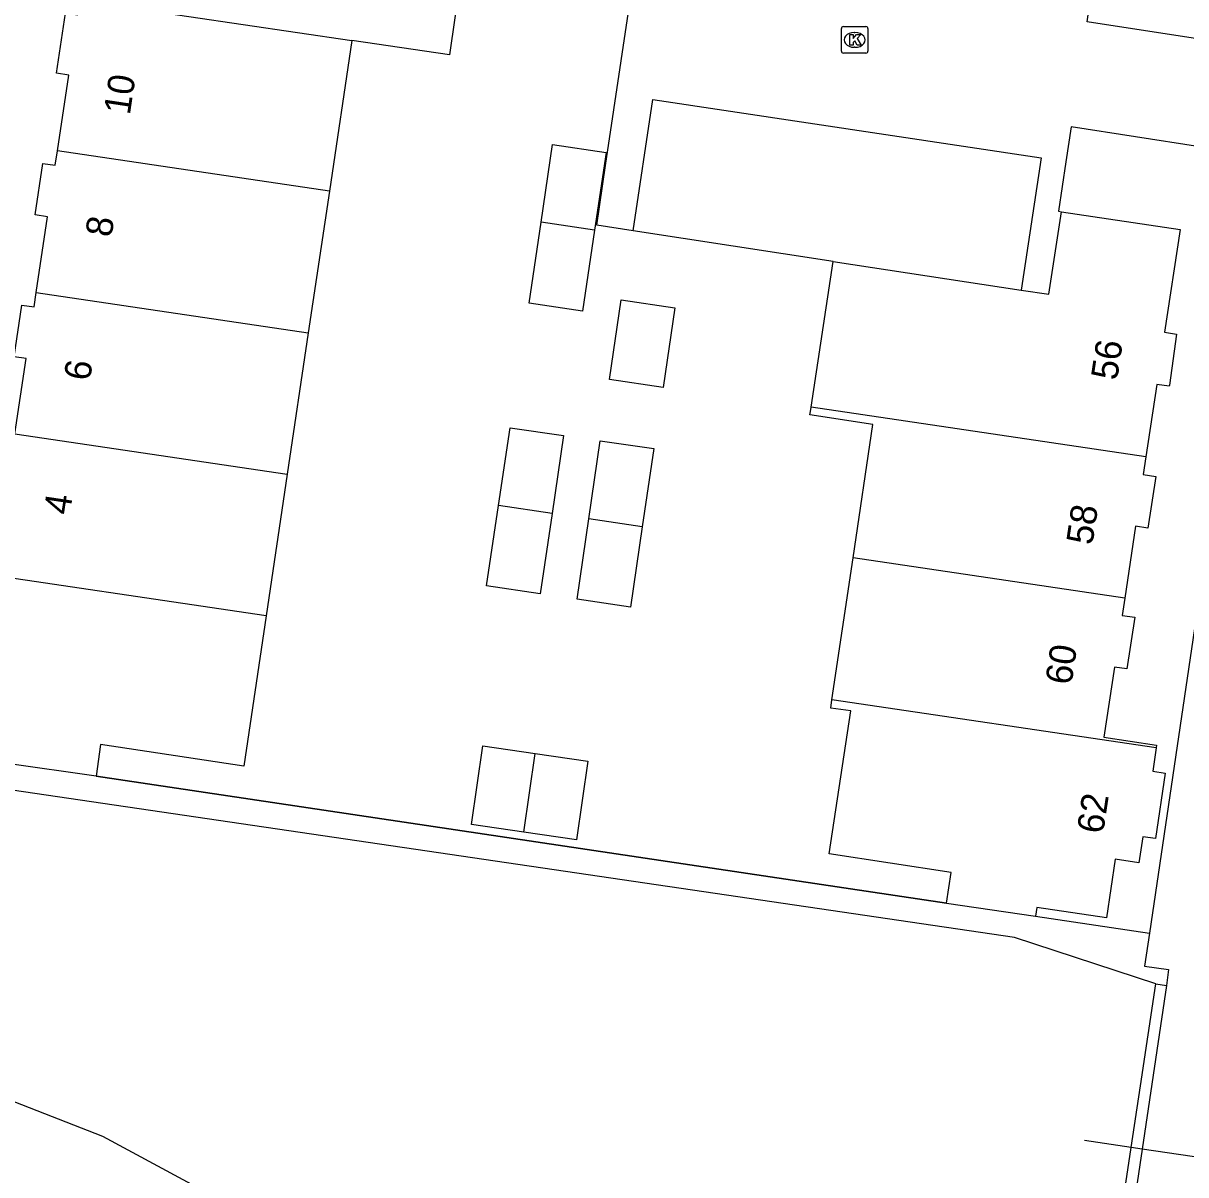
# Model space of a CAD drawing. Extents: x 164150 to 165261, y 382513 to 383432.
# Drawn here: x 164339.4 to 164383.22, y 382881.72 to 382925.13 of the extents above; entities that cross this region are included whole.
import ezdxf

# ---------------------------------------------------------------- set-up
doc = ezdxf.new("R2010")
doc.units = 0
for name, color, linetype in [('IMGEO_Duiker', 7, 'Continuous'), ('IMGEO_Greppel_droge_sloot', 7, 'Continuous'), ('IMGEO_Groenvoorziening', 7, 'Continuous'), ('IMGEO_Kolk', 7, 'Continuous'), ('IMGEO_Muur', 7, 'Continuous'), ('IMGEO_Pand', 7, 'Continuous'), ('IMGEO_Pand_nummerreeks', 7, 'Continuous'), ('IMGEO_Parkeervlak_open', 7, 'Continuous'), ('IMGEO_Rijbaan_lokaal_open', 7, 'Continuous'), ('IMGEO_Voetpad_open', 7, 'Continuous')]:
    doc.layers.add(name, color=color, linetype=linetype)

msp = doc.modelspace()

# ---------------------------------------------------------------- linework, layer by layer
at = {"layer": 'IMGEO_Duiker'}
msp.add_lwpolyline([(164394.254, 382880.819), (164392.537, 382881.072), (164392.122, 382881.133), (164381.579, 382882.687), (164381.166, 382882.748), (164379.407, 382883.007)], dxfattribs=at)
at = {"layer": 'IMGEO_Greppel_droge_sloot'}
for points in [[(164382.088, 382888.915), (164376.77, 382890.66), (164335.456, 382896.737), (164333.916, 382896.025)], [(164331.978, 382883.118), (164337.42, 382885.111), (164342.387, 382883.177), (164346.526, 382880.937), (164353.204, 382878.84), (164360.537, 382880.438), (164366.224, 382880.38), (164369.317, 382880.03), (164371.665, 382878.387), (164373.755, 382876.443), (164376.26, 382874.804), (164380.157, 382875.992)]]:
    msp.add_lwpolyline(points, dxfattribs=at)
at = {"layer": 'IMGEO_Groenvoorziening'}
for points in [[(164342.146, 382896.75), (164374.206, 382891.958)], [(164377.559, 382891.461), (164381.848, 382890.825)]]:
    msp.add_lwpolyline(points, dxfattribs=at)
at = {"layer": 'IMGEO_Kolk'}
for p, q in [((164370.238, 382924.079), (164370.238, 382924.931)), ((164370.313, 382925.005), (164371.165, 382925.005)), ((164370.726, 382924.785), (164370.751, 382924.785)), ((164371.239, 382924.931), (164371.239, 382924.079)), ((164371.165, 382924.005), (164370.313, 382924.005)), ((164370.749, 382924.225), (164370.724, 382924.225))]:
    msp.add_line(p, q, dxfattribs=at)
for points in [[(164370.238, 382924.079), (164370.238, 382924.931)], [(164370.313, 382925.005), (164371.165, 382925.005)], [(164371.239, 382924.931), (164371.239, 382924.079)], [(164370.559, 382924.705), (164370.682, 382924.705), (164370.682, 382924.554), (164370.812, 382924.705), (164370.976, 382924.705), (164370.83, 382924.554), (164370.983, 382924.305), (164370.831, 382924.305), (164370.746, 382924.469), (164370.682, 382924.402), (164370.682, 382924.305), (164370.559, 382924.305), (164370.559, 382924.705)], [(164371.165, 382924.005), (164370.313, 382924.005)]]:
    msp.add_lwpolyline(points, dxfattribs=at)
for centre, start, end in [((164370.315, 382924.929), 91.552, 178.448), ((164370.315, 382924.929), 91.552, 178.448), ((164371.163, 382924.929), 1.552, 88.448), ((164371.163, 382924.929), 1.552, 88.448), ((164370.315, 382924.081), 181.552, 268.448), ((164370.315, 382924.081), 181.552, 268.448), ((164371.163, 382924.081), 271.552, 358.448), ((164371.163, 382924.081), 271.552, 358.448)]:
    msp.add_arc(centre, 0.0765, start, end, dxfattribs=at)
for centre, major_axis, ratio, start_param, end_param in [((164370.725, 382924.505), (-0.387, 0.002), 0.722429, 4.712389, 7.853982), ((164370.75, 382924.505), (-0.39, 0.002), 0.717154, 1.570796, 4.712389)]:
    msp.add_ellipse(centre, major_axis=major_axis, ratio=ratio, start_param=start_param, end_param=end_param, dxfattribs=at)
at = {"layer": 'IMGEO_Muur'}
for points in [[(164374.206, 382891.958), (164342.146, 382896.75)], [(164380.157, 382875.992), (164380.851, 382880.641), (164381.166, 382882.748), (164381.513, 382885.072), (164382.088, 382888.915)], [(164382.495, 382888.849), (164381.579, 382882.687), (164380.573, 382875.921)], [(164382.088, 382888.915), (164382.495, 382888.849)]]:
    msp.add_lwpolyline(points, dxfattribs=at)
at = {"layer": 'IMGEO_Pand'}
for points in [[(164353.663, 382929.996), (164353.614, 382929.694), (164356.229, 382929.27), (164355.46, 382923.936), (164351.782, 382924.48)], [(164340.686, 382920.324), (164341.114, 382923.18), (164340.654, 382923.249), (164340.994, 382925.518), (164341.454, 382925.449), (164341.536, 382925.996)], [(164341.536, 382925.996), (164351.782, 382924.48)], [(164351.782, 382924.48), (164350.938, 382918.807)], [(164358.915, 382917.627), (164359.347, 382920.563), (164361.369, 382920.263), (164360.934, 382917.328)], [(164339.885, 382914.981), (164340.313, 382917.838), (164339.848, 382917.913), (164340.138, 382919.845), (164340.604, 382919.777), (164340.686, 382920.324)], [(164350.938, 382918.807), (164340.686, 382920.324)], [(164350.938, 382918.807), (164350.142, 382913.463)], [(164377.017, 382915.072), (164378.064, 382914.912), (164378.531, 382918.027)], [(164378.531, 382918.027), (164383.005, 382917.362), (164382.422, 382913.479), (164382.875, 382913.408), (164382.602, 382911.482), (164382.596, 382911.446), (164382.128, 382911.516), (164381.719, 382908.79)], [(164360.934, 382917.328), (164360.483, 382914.282), (164358.466, 382914.581), (164358.915, 382917.627)], [(164360.934, 382917.328), (164358.915, 382917.627)], [(164369.096, 382910.658), (164369.928, 382916.155)], [(164369.928, 382916.155), (164377.017, 382915.072)], [(164339.085, 382909.646), (164339.511, 382912.487), (164339.05, 382912.557), (164339.343, 382914.5), (164339.803, 382914.436), (164339.885, 382914.981)], [(164339.885, 382914.981), (164350.142, 382913.463)], [(164363.96, 382914.408), (164363.517, 382911.404), (164361.495, 382911.705), (164361.942, 382914.708), (164363.96, 382914.408)], [(164350.142, 382913.463), (164349.347, 382908.128)], [(164370.679, 382904.972), (164371.429, 382910.007), (164369.052, 382910.366), (164369.071, 382910.492), (164369.096, 382910.658)], [(164381.719, 382908.79), (164369.096, 382910.658)], [(164357.313, 382906.95), (164357.748, 382909.883), (164359.768, 382909.585), (164359.335, 382906.651)], [(164339.085, 382909.646), (164349.347, 382908.128)], [(164360.716, 382906.446), (164361.148, 382909.39), (164363.167, 382909.094), (164362.734, 382906.147)], [(164381.719, 382908.79), (164381.618, 382908.116), (164382.088, 382908.046), (164381.796, 382906.098), (164381.326, 382906.168), (164380.919, 382903.456)], [(164349.347, 382908.128), (164348.551, 382902.785)], [(164359.335, 382906.651), (164358.887, 382903.618), (164356.864, 382903.917), (164357.313, 382906.95)], [(164359.335, 382906.651), (164357.313, 382906.95)], [(164362.734, 382906.147), (164362.289, 382903.118), (164360.272, 382903.414), (164360.716, 382906.446)], [(164362.734, 382906.147), (164360.716, 382906.446)], [(164369.883, 382899.628), (164370.679, 382904.972)], [(164380.919, 382903.456), (164370.679, 382904.972)], [(164348.551, 382902.785), (164336.317, 382904.596)], [(164380.919, 382903.456), (164380.822, 382902.806), (164381.297, 382902.735), (164381.005, 382900.787), (164380.53, 382900.858), (164380.134, 382898.216), (164382.123, 382897.915), (164382.109, 382897.819)], [(164348.551, 382902.785), (164347.707, 382897.116), (164342.311, 382897.934), (164342.146, 382896.75)], [(164374.206, 382891.958), (164374.382, 382893.116), (164369.782, 382893.81), (164370.598, 382899.206), (164369.836, 382899.311), (164369.883, 382899.628)], [(164382.109, 382897.819), (164369.883, 382899.628)], [(164358.271, 382894.63), (164356.292, 382894.916), (164356.722, 382897.888), (164358.701, 382897.602)], [(164382.109, 382897.819), (164381.975, 382896.927), (164382.449, 382896.853), (164382.08, 382894.388), (164381.605, 382894.46), (164381.458, 382893.481), (164380.561, 382893.614), (164380.232, 382891.398), (164377.608, 382891.787), (164377.559, 382891.461)], [(164342.146, 382896.75), (164338.789, 382897.217)], [(164358.701, 382897.602), (164360.681, 382897.315), (164360.25, 382894.343), (164358.271, 382894.63)], [(164358.271, 382894.63), (164358.701, 382897.602)], [(164374.206, 382891.958), (164377.559, 382891.461)]]:
    msp.add_lwpolyline(points, dxfattribs=at)
at = {"layer": 'IMGEO_Parkeervlak_open'}
msp.add_lwpolyline([(164369.928, 382916.155), (164362.394, 382917.305)], dxfattribs=at)
at = {"layer": 'IMGEO_Rijbaan_lokaal_open'}
for points in [[(164362.394, 382917.305), (164361.014, 382917.516), (164361.351, 382919.771), (164363.474, 382933.973), (164364.842, 382933.776)], [(164386.768, 382924.065), (164379.499, 382925.189), (164379.674, 382926.423), (164379.973, 382928.387), (164380.072, 382928.372)], [(164362.394, 382917.305), (164363.127, 382922.256), (164377.768, 382920.053), (164377.017, 382915.072)], [(164386.181, 382920.095), (164378.902, 382921.233), (164378.704, 382919.912), (164378.422, 382918.043), (164378.531, 382918.027)]]:
    msp.add_lwpolyline(points, dxfattribs=at)
at = {"layer": 'IMGEO_Voetpad_open'}
for points in [[(164386.181, 382920.095), (164381.848, 382890.825)], [(164381.848, 382890.825), (164381.663, 382889.579), (164382.566, 382889.449), (164382.495, 382888.849)]]:
    msp.add_lwpolyline(points, dxfattribs=at)

# ---------------------------------------------------------------- texts
at = {"layer": 'IMGEO_Pand_nummerreeks'}
for s, rotation, p in [('10', 81.4746, (164343.413, 382921.649)), ('8', 81.4746, (164342.721, 382917.039)), ('56', 81.4689, (164380.63, 382911.643)), ('6', 81.4803, (164341.909, 382911.622)), ('4', 81.4861, (164341.152, 382906.567)), ('58', 81.4746, (164379.699, 382905.433)), ('60', 81.4746, (164378.908, 382900.155)), ('62', 81.4631, (164380.101, 382894.542))]:
    msp.add_text(s, height=1, rotation=rotation, dxfattribs=at).set_placement(p)

doc.saveas('drawing.dxf')
